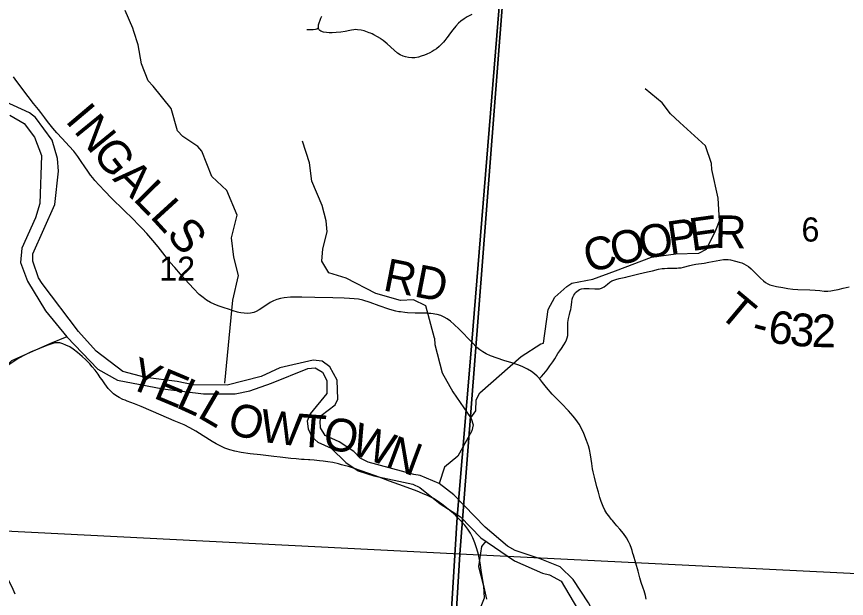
# Model space of a CAD drawing. Extents: x 0 to 34, y 0 to 22.
# Drawn here: x 4.109 to 5.548, y 14.883 to 15.893 of the extents above; entities that cross this region are included whole.
import ezdxf

# ---------------------------------------------------------------- set-up
doc = ezdxf.new("R2010")
doc.units = 0
for name, color, linetype in [('Default', 7, 'Continuous'), ('GM_X_County_Road', 7, 'Continuous'), ('GM_X_County_Road_Text', 7, 'Continuous'), ('GM_X_Major_River', 7, 'Continuous'), ('GM_X_Minor_River', 7, 'Continuous'), ('GM_X_Section', 7, 'Continuous'), ('GM_X_Section_Text', 7, 'Continuous'), ('GM_X_Township_Road', 7, 'Continuous'), ('GM_X_Township_Road_Text', 7, 'Continuous')]:
    doc.layers.add(name, color=color, linetype=linetype)

msp = doc.modelspace()

# ---------------------------------------------------------------- linework, layer by layer
at = {"layer": 'Default'}
for points in [[(2.1, 16.1239), (2.1, 14.1), (4.8164, 14.1), (4.8734, 15.0246), (4.8987, 15.3279), (4.9458, 15.9099), (4.9525, 15.9829), (4.6644, 15.9921), (3.9292, 16.0191), (3.6368, 16.0331), (2.1721, 16.1195)], [(3.7808, 14.1), (4.8257, 14.1), (4.8777, 14.9601), (3.8368, 15.0128)], [(4.8257, 14.1), (5.8897, 14.1), (5.8935, 14.1589), (5.91, 14.4183), (5.9253, 14.6691), (5.9405, 14.9074), (4.8777, 14.9601)]]:
    msp.add_lwpolyline(points, close=True, dxfattribs=at)
msp.add_lwpolyline([(4.9458, 15.9099), (4.8987, 15.3279), (4.8734, 15.0246), (4.8164, 14.1), (8.0885, 14.1)], dxfattribs=at)
at = {"layer": 'GM_X_County_Road'}
for points in [[(4.8984, 15.8966), (4.8906, 15.8926), (4.8853, 15.8894), (4.8797, 15.8853), (4.8755, 15.8816), (4.8708, 15.8765), (4.8657, 15.8702), (4.8597, 15.8624), (4.8575, 15.8593), (4.855, 15.856), (4.8516, 15.8514), (4.8492, 15.8486), (4.8454, 15.8445), (4.8418, 15.8412), (4.837, 15.8373), (4.8334, 15.8348), (4.8298, 15.8325), (4.8255, 15.83), (4.8205, 15.8277), (4.8165, 15.8261), (4.8107, 15.8242), (4.8059, 15.8229), (4.7998, 15.8218), (4.7943, 15.8216), (4.7888, 15.822), (4.7834, 15.823), (4.7794, 15.8244), (4.7744, 15.8268), (4.7698, 15.8299), (4.7641, 15.8346), (4.7518, 15.8459), (4.7445, 15.8517), (4.7415, 15.8539), (4.7399, 15.8549), (4.7351, 15.8578), (4.7286, 15.8615), (4.7258, 15.8629), (4.723, 15.8642), (4.7207, 15.8651), (4.7148, 15.8672), (4.7119, 15.8681), (4.7064, 15.8695), (4.7002, 15.8702), (4.6968, 15.8704), (4.694, 15.8702), (4.6901, 15.8696), (4.687, 15.8691), (4.6789, 15.867), (4.6713, 15.866), (4.6632, 15.8653), (4.6565, 15.8651), (4.6509, 15.8651), (4.6462, 15.8655), (4.641, 15.8662), (4.6364, 15.868), (4.6347, 15.8691), (4.6336, 15.8702), (4.6331, 15.8711), (4.6327, 15.8723), (4.6325, 15.8734), (4.6324, 15.8761), (4.6327, 15.8787), (4.6337, 15.8822), (4.6353, 15.8866), (4.6369, 15.8906), (4.6383, 15.894)], [(4.3832, 15.4575), (4.3825, 15.4582), (4.376, 15.4657), (4.3663, 15.4778), (4.3542, 15.4936), (4.3453, 15.5048), (4.335, 15.5165), (4.3269, 15.5251), (4.3205, 15.5319), (4.3103, 15.5419), (4.2947, 15.5571), (4.2735, 15.578), (4.2617, 15.5899), (4.2519, 15.6003), (4.2445, 15.6086), (4.2408, 15.6134), (4.2373, 15.6179), (4.2322, 15.6251), (4.2273, 15.6324), (4.221, 15.6414), (4.2151, 15.6505), (4.2079, 15.6595), (4.2, 15.6684), (4.1876, 15.6815), (4.1784, 15.6915), (4.1716, 15.6996), (4.1627, 15.7112), (4.158, 15.7173), (4.151, 15.7265), (4.1466, 15.7321), (4.1384, 15.7422), (4.1287, 15.7543), (4.1094, 15.7806), (4.1036, 15.7883)], [(4.8989, 15.3273), (4.8765, 15.3507), (4.868, 15.359), (4.8614, 15.3647), (4.8559, 15.3688), (4.8504, 15.3718), (4.8446, 15.3742), (4.8386, 15.376), (4.8343, 15.3769), (4.8313, 15.3775), (4.8276, 15.3779), (4.8245, 15.3781), (4.8203, 15.3783), (4.8178, 15.3783), (4.8098, 15.3782), (4.8005, 15.3782), (4.7869, 15.379), (4.7826, 15.3794), (4.7747, 15.3805), (4.7722, 15.381), (4.7668, 15.382), (4.7602, 15.3837), (4.7543, 15.3855), (4.7478, 15.3876), (4.7449, 15.3886), (4.7379, 15.3912), (4.7221, 15.3969), (4.7096, 15.4009), (4.7017, 15.4027), (4.6943, 15.4036), (4.6862, 15.4041), (4.6769, 15.4046), (4.6576, 15.4052), (4.626, 15.4057), (4.6037, 15.4061), (4.5931, 15.4062), (4.5838, 15.406), (4.5732, 15.4052), (4.5664, 15.4041), (4.5604, 15.4024), (4.5546, 15.4), (4.549, 15.3971), (4.5412, 15.392), (4.5296, 15.384), (4.5247, 15.3814), (4.5202, 15.3798), (4.5148, 15.3786), (4.5093, 15.3781), (4.5038, 15.3783), (4.4977, 15.3792), (4.4941, 15.3799), (4.4923, 15.3804), (4.4846, 15.3826), (4.4746, 15.3859), (4.4705, 15.3872), (4.4587, 15.3913), (4.4518, 15.3939), (4.4451, 15.397), (4.4381, 15.401), (4.4322, 15.4054), (4.4257, 15.4111), (4.4156, 15.4212), (4.4014, 15.4369), (4.3932, 15.4462), (4.3832, 15.4575)], [(5.2008, 14.8819), (5.1996, 14.8887), (5.1974, 14.8964), (5.1958, 14.9011), (5.1925, 14.9113), (5.1902, 14.9192), (5.1869, 14.9308), (5.183, 14.9445), (5.179, 14.9584), (5.1781, 14.9614), (5.1766, 14.9665), (5.1754, 14.9703), (5.1732, 14.9767), (5.1705, 14.9824), (5.1667, 14.9888), (5.1614, 14.9964), (5.1554, 15.0035), (5.1501, 15.0095), (5.1472, 15.0127), (5.1425, 15.0184), (5.1405, 15.0208), (5.1361, 15.0268), (5.1329, 15.0311), (5.1293, 15.0369), (5.1262, 15.0429), (5.1228, 15.0515), (5.1205, 15.0586), (5.1181, 15.0676), (5.1156, 15.0772), (5.1111, 15.094), (5.109, 15.103), (5.108, 15.1085), (5.1067, 15.1177), (5.1046, 15.1324), (5.1026, 15.1416), (5.1008, 15.1482), (5.0975, 15.1576), (5.0927, 15.1697), (5.0883, 15.1794), (5.0847, 15.186), (5.0818, 15.19), (5.079, 15.1941), (5.0744, 15.2), (5.0665, 15.2088), (5.0539, 15.2217), (5.0456, 15.2301), (5.0378, 15.2381), (5.0281, 15.2493), (5.0213, 15.2581), (5.0159, 15.265), (5.0121, 15.2692), (5.0074, 15.2733), (5.0018, 15.2774), (4.9949, 15.2815), (4.986, 15.2859), (4.9785, 15.2889), (4.9678, 15.2925), (4.9542, 15.2966), (4.9423, 15.3004), (4.9307, 15.3047), (4.9234, 15.308), (4.9174, 15.3112), (4.9124, 15.3147), (4.9072, 15.3191), (4.8989, 15.3273)]]:
    msp.add_lwpolyline(points, dxfattribs=at)
at = {"layer": 'GM_X_Major_River'}
for points in [[(4.216, 15.3467), (4.153, 15.4298), (4.1469, 15.44), (4.137, 15.4684), (4.1369, 15.4813), (4.1749, 15.5672), (4.1816, 15.6249), (4.1796, 15.6469), (4.1704, 15.6784), (4.1415, 15.7181), (4.1313, 15.7261), (4.0896, 15.7453)], [(4.0972, 15.7222), (4.1219, 15.7074), (4.1401, 15.6836), (4.152, 15.6518), (4.1492, 15.5687), (4.1417, 15.544), (4.1179, 15.4915), (4.1154, 15.4661), (4.128, 15.4339), (4.1588, 15.3827), (4.1959, 15.3376)], [(5.0169, 14.9523), (4.9874, 14.9619), (4.9738, 14.9664), (4.9605, 14.9743), (4.9219, 15.0072), (4.8676, 15.0631), (4.8418, 15.0828), (4.8092, 15.0967), (4.7979, 15.0986), (4.7187, 15.1199), (4.7051, 15.1271), (4.6941, 15.1385), (4.6687, 15.1554), (4.6444, 15.166), (4.6361, 15.1792), (4.6353, 15.191), (4.6372, 15.2008), (4.6617, 15.2195), (4.6659, 15.229), (4.665, 15.262), (4.6525, 15.2854), (4.6389, 15.2952), (4.6233, 15.2971), (4.5655, 15.2837), (4.5333, 15.2684), (4.4739, 15.2535), (4.4153, 15.254), (4.3876, 15.26), (4.3327, 15.2671), (4.2933, 15.2772), (4.2467, 15.3127), (4.216, 15.3467)], [(4.1959, 15.3376), (4.2498, 15.2812), (4.2839, 15.2624), (4.3623, 15.2471), (4.4331, 15.2382), (4.488, 15.2383), (4.5133, 15.2437), (4.5511, 15.2567), (4.6143, 15.2823), (4.6268, 15.2838), (4.6397, 15.2759), (4.6469, 15.2615), (4.6469, 15.2388), (4.6179, 15.2038), (4.613, 15.1913), (4.6149, 15.1777), (4.621, 15.164), (4.6316, 15.1546), (4.6547, 15.144), (4.6801, 15.1195), (4.7014, 15.1051), (4.7286, 15.0961), (4.7964, 15.0815), (4.8085, 15.0762), (4.8438, 15.0475), (4.8787, 15.0252), (4.9143, 14.9886), (4.9727, 14.9489), (5.0212, 14.9271), (5.0334, 14.9242)], [(5.5558, 14.6688), (5.4896, 14.6012), (5.4399, 14.563), (5.3541, 14.4817), (5.3273, 14.4637), (5.3137, 14.4602), (5.2986, 14.4582), (5.2858, 14.4608), (5.2744, 14.4695), (5.2705, 14.4823), (5.268, 14.5225), (5.2782, 14.6053), (5.2777, 14.6262), (5.2642, 14.6659), (5.2482, 14.689), (5.197, 14.7164), (5.1848, 14.7258), (5.1613, 14.7529), (5.1395, 14.7938), (5.1249, 14.8324), (5.1008, 14.8759), (5.0741, 14.9163), (5.0518, 14.9381), (5.0169, 14.9523)], [(5.0334, 14.9242), (5.0533, 14.9135), (5.1045, 14.827), (5.1363, 14.7528), (5.1538, 14.729), (5.1766, 14.7079), (5.2335, 14.6764), (5.2457, 14.6647), (5.2541, 14.6427), (5.2581, 14.6086), (5.2579, 14.5843), (5.2457, 14.5281), (5.2463, 14.4757), (5.2552, 14.4413), (5.253, 14.4287), (5.2478, 14.4162), (5.2614, 14.4125), (5.2958, 14.4206), (5.3358, 14.4398), (5.361, 14.4559), (5.41, 14.5006), (5.5146, 14.5968), (5.5898, 14.6758)]]:
    msp.add_lwpolyline(points, dxfattribs=at)
at = {"layer": 'GM_X_Minor_River'}
for points in [[(4.4702, 15.2567), (4.484, 15.4013), (4.4935, 15.4439), (4.4859, 15.4759), (4.4818, 15.5093), (4.4916, 15.5485), (4.4735, 15.5914), (4.4477, 15.6154), (4.4299, 15.6594), (4.4234, 15.6678), (4.3973, 15.6853), (4.3882, 15.6948), (4.3772, 15.7335), (4.3458, 15.7723), (4.3371, 15.7814), (4.3257, 15.8114), (4.32, 15.8441), (4.3124, 15.8673), (4.3106, 15.873), (4.2969, 15.9034)], [(5.023, 15.3262), (5.031, 15.3848), (5.0424, 15.4061), (5.0636, 15.4247), (5.072, 15.4305), (5.1083, 15.4373), (5.1478, 15.4518), (5.21, 15.4755), (5.2524, 15.4812), (5.2922, 15.4828), (5.3055, 15.4893), (5.3218, 15.5227), (5.3283, 15.5387), (5.326, 15.5779), (5.315, 15.6277), (5.3143, 15.6383), (5.304, 15.6691), (5.2597, 15.7094), (5.243, 15.7242), (5.2286, 15.7432), (5.1995, 15.7678)], [(4.834, 15.3348), (4.8187, 15.3914), (4.7975, 15.4017), (4.7747, 15.4005), (4.7319, 15.4126), (4.6808, 15.4392), (4.6504, 15.4487), (4.6383, 15.4688), (4.6402, 15.4901), (4.6474, 15.5194), (4.6459, 15.5384), (4.6391, 15.565), (4.6209, 15.6076), (4.6168, 15.6395), (4.605, 15.6767)], [(4.1959, 15.3376), (4.1676, 15.326), (4.0999, 15.2957), (4.0761, 15.2743), (4.0471, 15.2385), (4.0354, 15.2323), (4.0002, 15.2143), (3.9908, 15.2032), (3.9769, 15.1698), (3.9382, 15.1115), (3.933, 15.0955), (3.9354, 15.0727), (3.9408, 15.0617), (3.9534, 15.0489), (4.0086, 15.0165), (4.0479, 14.9871), (4.0896, 14.9273), (4.095, 14.9144), (4.1008, 14.9038), (4.1058, 14.8913)], [(4.834, 15.3348), (4.8341, 15.3241), (4.8469, 15.2748), (4.8657, 15.2419), (4.8975, 15.1957), (4.9006, 15.1844), (4.8987, 15.1741), (4.874, 15.1303), (4.8513, 15.1112), (4.8418, 15.0828)], [(4.8966, 15.197), (4.9054, 15.2091), (4.906, 15.228), (4.9124, 15.2402), (4.9841, 15.3033), (5.0185, 15.3251), (5.023, 15.3262)], [(4.9226, 14.9829), (4.9151, 14.9737), (4.9104, 14.9387), (4.919, 14.9053), (4.9199, 14.8837), (4.912, 14.8635), (4.8728, 14.8276), (4.803, 14.757), (4.738, 14.7115), (4.687, 14.6672)]]:
    msp.add_lwpolyline(points, dxfattribs=at)
at = {"layer": 'GM_X_Section'}
for points in [[(3.8924, 16.0203), (4.9447, 15.9846), (4.9568, 15.9843), (4.8777, 14.9601), (3.8368, 15.0128)], [(4.9568, 15.9843), (6.0049, 15.9328), (5.9932, 15.6936), (5.9754, 15.4391), (5.9587, 15.1787), (5.9407, 14.9107), (5.9405, 14.9074), (4.8777, 14.9601)]]:
    msp.add_lwpolyline(points, close=True, dxfattribs=at)
at = {"layer": 'GM_X_Township_Road'}
for points in [[(4.6125, 15.8707), (4.6162, 15.8704), (4.6187, 15.8704), (4.6233, 15.8706), (4.6273, 15.8711), (4.6297, 15.872), (4.6325, 15.8734)], [(5.0159, 15.265), (5.0192, 15.2686), (5.0234, 15.2732), (5.0293, 15.2804), (5.0341, 15.2869), (5.039, 15.294), (5.0423, 15.2992), (5.0479, 15.3082), (5.0514, 15.3133), (5.0539, 15.3169), (5.0584, 15.3236), (5.0612, 15.3284), (5.063, 15.3323), (5.0642, 15.3358), (5.0649, 15.3395), (5.0652, 15.3432), (5.0651, 15.3575), (5.0654, 15.3624), (5.0657, 15.3655), (5.0664, 15.3692), (5.0669, 15.3716), (5.0681, 15.3764), (5.0694, 15.3812), (5.0702, 15.3848), (5.0708, 15.3885), (5.072, 15.3984), (5.0728, 15.4026), (5.0739, 15.4062), (5.0754, 15.4096), (5.0771, 15.4122), (5.0786, 15.4142), (5.0809, 15.4163), (5.0829, 15.4178), (5.0856, 15.4193), (5.0891, 15.4205), (5.0928, 15.4211), (5.0965, 15.4213), (5.1021, 15.4211), (5.112, 15.4205), (5.1164, 15.4205), (5.1201, 15.4209), (5.1237, 15.4219), (5.1259, 15.4229), (5.128, 15.4243), (5.1337, 15.429), (5.1382, 15.4324), (5.1414, 15.4343), (5.1448, 15.4358), (5.1483, 15.437), (5.1543, 15.4385), (5.1659, 15.441), (5.1695, 15.442), (5.1719, 15.4425), (5.1882, 15.4465), (5.2033, 15.4499), (5.2118, 15.4519), (5.2226, 15.4546), (5.2287, 15.4557), (5.2331, 15.4562), (5.238, 15.4563), (5.2479, 15.4563), (5.2517, 15.4564), (5.2541, 15.4566), (5.2572, 15.4569), (5.2615, 15.4574), (5.2658, 15.4582), (5.2767, 15.4609), (5.2815, 15.4621), (5.287, 15.4632), (5.3017, 15.4653), (5.3096, 15.4667), (5.3286, 15.4702), (5.3353, 15.4714), (5.3396, 15.4717), (5.3433, 15.4715), (5.3476, 15.4709), (5.356, 15.4689), (5.3626, 15.4672), (5.3667, 15.4658), (5.3707, 15.4641), (5.3745, 15.462), (5.3785, 15.4592), (5.3832, 15.4552), (5.3897, 15.4488), (5.3947, 15.4436), (5.3991, 15.4393), (5.4043, 15.4348), (5.4083, 15.4318), (5.412, 15.4296), (5.4153, 15.4279), (5.42, 15.4263), (5.4271, 15.4248), (5.4383, 15.4229), (5.447, 15.4213), (5.4555, 15.4199), (5.4642, 15.4194), (5.4851, 15.4187), (5.4943, 15.4181), (5.5025, 15.4175), (5.51, 15.4168), (5.516, 15.4168), (5.5211, 15.4172), (5.5269, 15.4182), (5.5343, 15.4198), (5.5425, 15.422), (5.553, 15.4243)], [(4.8743, 15.0234), (4.8736, 15.0241), (4.87, 15.0277), (4.8603, 15.036), (4.8489, 15.0452), (4.8399, 15.0517), (4.8318, 15.0569), (4.8228, 15.0615), (4.813, 15.0658), (4.8035, 15.0693), (4.78, 15.078), (4.7557, 15.0871), (4.7377, 15.0938), (4.7197, 15.1004), (4.6918, 15.1099), (4.6845, 15.1121), (4.6771, 15.1142), (4.6722, 15.1155), (4.667, 15.1169), (4.6574, 15.1192), (4.6489, 15.1207), (4.6409, 15.1216), (4.6342, 15.1224), (4.6298, 15.1229), (4.625, 15.1232), (4.6176, 15.1238), (4.6151, 15.124), (4.6077, 15.1245), (4.6028, 15.1247), (4.5937, 15.1254), (4.5845, 15.1263), (4.5663, 15.1288), (4.5553, 15.1298), (4.5318, 15.1324), (4.5139, 15.1346), (4.4985, 15.1369), (4.4875, 15.1391), (4.4785, 15.1415), (4.4703, 15.1444), (4.4618, 15.1484), (4.4551, 15.152), (4.4481, 15.1557), (4.4324, 15.1657), (4.4197, 15.1737), (4.4094, 15.1796), (4.3993, 15.1847), (4.382, 15.1918), (4.3595, 15.2013), (4.3247, 15.2164), (4.3132, 15.2209), (4.3009, 15.2257), (4.2969, 15.2273), (4.2934, 15.2287), (4.2867, 15.232), (4.2808, 15.2356), (4.2769, 15.2387), (4.2732, 15.2421), (4.2678, 15.248), (4.2647, 15.2519), (4.2617, 15.2558), (4.2571, 15.2625), (4.2539, 15.2671), (4.2503, 15.2724), (4.2452, 15.2794), (4.2402, 15.2856), (4.2361, 15.2903), (4.2321, 15.2943), (4.2287, 15.2976), (4.2228, 15.3032), (4.2188, 15.3067), (4.2145, 15.3104), (4.2071, 15.316), (4.2009, 15.3199), (4.1943, 15.3232), (4.1892, 15.3253), (4.1838, 15.3267), (4.1796, 15.3271), (4.1754, 15.3268), (4.17, 15.3255), (4.1613, 15.3223), (4.1487, 15.3172), (4.1328, 15.3107), (4.1227, 15.3057), (4.1125, 15.3002), (4.0925, 15.2869)], [(4.9245, 14.8822), (4.9202, 14.9029), (4.9191, 14.9083), (4.9156, 14.9285), (4.9128, 14.9451), (4.9099, 14.9595), (4.9072, 14.9697), (4.904, 14.9798), (4.9002, 14.9886), (4.8962, 14.9966), (4.8917, 15.0038), (4.8866, 15.0104), (4.8797, 15.018), (4.8743, 15.0234)]]:
    msp.add_lwpolyline(points, dxfattribs=at)

# ---------------------------------------------------------------- texts
at = {"layer": 'GM_X_County_Road_Text'}
for s, height, rotation, p in [('I', 0.0568, 310.1619, (4.1919, 15.7119)), ('N', 0.0568, 309.1815, (4.2068, 15.6942)), ('G', 0.0568, 307.9566, (4.2382, 15.6557)), ('A', 0.0568, 315.0572, (4.274, 15.6106)), ('L', 0.0568, 314.6167, (4.3093, 15.5753)), ('L', 0.0568, 312.4173, (4.3388, 15.5455)), ('S', 0.0568, 309.6705, (4.367, 15.5147)), ('RD', 0.05682, 348.9822, (4.7426, 15.4183))]:
    msp.add_text(s, height=height, rotation=rotation, dxfattribs=at).set_placement(p)
at = {"layer": 'GM_X_Section_Text'}
for s, height, p in [('6', 0.0419, (5.4704, 15.5027)), ('12', 0.04186, (4.3562, 15.4347))]:
    msp.add_text(s, height=height, rotation=0, dxfattribs=at).set_placement(p)
at = {"layer": 'GM_X_Township_Road_Text'}
for s, rotation, p in [('E', 7.848, (5.28, 15.4861)), ('R', 358.7197, (5.3197, 15.4918)), ('O', 11.0106, (5.1938, 15.4712)), ('P', 8.2655, (5.2422, 15.4806)), ('O', 13.1448, (5.1457, 15.4599)), ('C', 15.1618, (5.1011, 15.4479)), ('T', 319.9519, (5.3243, 15.3755)), ('6', 351.5629, (5.4102, 15.3284)), ('3', 355.2612, (5.4488, 15.3228)), ('2', 358.8557, (5.4876, 15.3198)), ('-', 345.4327, (5.3812, 15.3356)), ('Y', 337.4034, (4.2983, 15.2513)), ('E', 337.3228, (4.3444, 15.2321)), ('L', 335.5532, (4.3832, 15.2159)), ('L', 329.6834, (4.4205, 15.1991)), ('O', 344.1316, (4.4716, 15.1715)), ('W', 352.8935, (4.529, 15.1559)), ('T', 355.6405, (4.5972, 15.1475)), ('O', 349.1734, (4.6379, 15.1445)), ('W', 340.6512, (4.6849, 15.1357)), ('N', 339.536, (4.7467, 15.114))]:
    msp.add_text(s, height=0.0568, rotation=rotation, dxfattribs=at).set_placement(p)

doc.saveas('drawing.dxf')
